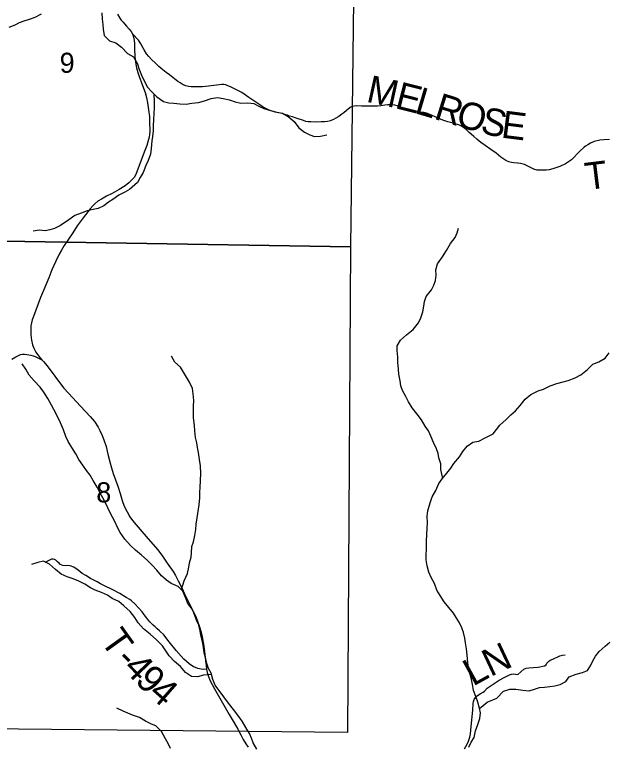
# Model space of a CAD drawing. Extents: x 0 to 34, y 0 to 22.
# Drawn here: x 25.315 to 26.547, y 15.526 to 17.051 of the extents above; entities that cross this region are included whole.
import ezdxf

# ---------------------------------------------------------------- set-up
doc = ezdxf.new("R2010")
doc.units = 0
for name, color, linetype in [('GM_X_Corporation', 7, 'Continuous'), ('GM_X_County_Road', 7, 'Continuous'), ('GM_X_Minor_River', 7, 'Continuous'), ('GM_X_Section_Text', 7, 'Continuous'), ('GM_X_Township_Road', 7, 'Continuous'), ('GM_X_Township_Road_Text', 7, 'Continuous')]:
    doc.layers.add(name, color=color, linetype=linetype)

msp = doc.modelspace()

# ---------------------------------------------------------------- linework, layer by layer
at = {"layer": 'GM_X_Corporation'}
for points in [[(26.0272, 17.5944), (26.0142, 16.5672), (24.9957, 16.5834), (25.0136, 17.617)], [(24.9957, 16.5834), (26.0142, 16.5672), (26.0085, 15.5549), (24.9795, 15.5656)]]:
    msp.add_lwpolyline(points, close=True, dxfattribs=at)
at = {"layer": 'GM_X_County_Road'}
for points in [[(25.5294, 17.0518), (25.5339, 17.0436), (25.537, 17.0394), (25.5399, 17.0357), (25.548, 17.0269), (25.5535, 17.0203), (25.5574, 17.0153), (25.5605, 17.0104), (25.5627, 17.0038), (25.5638, 16.9976), (25.5643, 16.9901), (25.5646, 16.9792), (25.5651, 16.9637), (25.5664, 16.9519), (25.5685, 16.9395), (25.5713, 16.9299), (25.574, 16.9219), (25.5763, 16.9159), (25.5787, 16.9103), (25.5834, 16.8976), (25.5865, 16.8881), (25.5893, 16.8777), (25.5916, 16.8666), (25.5937, 16.852), (25.5956, 16.8385), (25.5961, 16.8281), (25.5962, 16.8075), (25.5957, 16.8009), (25.5948, 16.7955), (25.5925, 16.7856), (25.59, 16.7779), (25.5846, 16.7638), (25.5697, 16.7231), (25.5667, 16.7164), (25.5636, 16.7116), (25.5584, 16.7057), (25.5527, 16.7005), (25.5448, 16.6943), (25.5323, 16.6862), (25.5179, 16.678), (25.5065, 16.6722), (25.4957, 16.6665), (25.4883, 16.6621), (25.482, 16.6566), (25.478, 16.6524), (25.4722, 16.6458), (25.4576, 16.6271), (25.445, 16.6103), (25.436, 16.5963), (25.4183, 16.5694), (25.4121, 16.5598), (25.4077, 16.5519), (25.4003, 16.5367), (25.3925, 16.5188), (25.3861, 16.5025), (25.3747, 16.4761), (25.3688, 16.4612), (25.3538, 16.4214), (25.3516, 16.4151), (25.35, 16.4088), (25.3489, 16.4021), (25.3484, 16.3938), (25.3483, 16.3836), (25.3498, 16.3722), (25.3519, 16.3628), (25.3548, 16.3559), (25.3589, 16.3476), (25.3647, 16.3395), (25.3712, 16.3316)], [(25.3712, 16.3316), (25.3753, 16.327), (25.3819, 16.3197), (25.3891, 16.3109), (25.4084, 16.2843), (25.4174, 16.2726), (25.427, 16.2621), (25.4519, 16.2351), (25.4724, 16.2137), (25.4813, 16.2031), (25.4887, 16.1913), (25.4922, 16.1843), (25.4974, 16.1739), (25.5009, 16.165), (25.5055, 16.1508), (25.5092, 16.135), (25.5129, 16.1188), (25.5166, 16.1061), (25.5203, 16.0948), (25.53, 16.0685), (25.5345, 16.0527), (25.5385, 16.0382), (25.5429, 16.0268), (25.5489, 16.0149), (25.5551, 16.0044), (25.5606, 15.9967), (25.5798, 15.9738), (25.598, 15.9529), (25.6132, 15.9356), (25.6228, 15.9225), (25.6329, 15.908), (25.645, 15.8903), (25.6498, 15.8822), (25.6557, 15.8711), (25.6638, 15.855), (25.6686, 15.8436), (25.6875, 15.8065), (25.6932, 15.7944), (25.696, 15.7871), (25.7002, 15.7748), (25.7033, 15.7641), (25.7056, 15.7545), (25.7089, 15.7347), (25.7113, 15.7178), (25.7125, 15.7053), (25.7134, 15.6989), (25.7138, 15.6948), (25.7147, 15.6871), (25.7162, 15.6799), (25.7181, 15.6735), (25.7217, 15.6642), (25.7262, 15.655), (25.7314, 15.6457), (25.7368, 15.6359), (25.7534, 15.6072), (25.7618, 15.5924), (25.772, 15.5754), (25.78, 15.5616), (25.7859, 15.5504), (25.7911, 15.5402), (25.7962, 15.5317), (25.801, 15.5244)]]:
    msp.add_lwpolyline(points, dxfattribs=at)
at = {"layer": 'GM_X_Minor_River'}
for points in [[(25.3703, 17.0513), (25.3567, 17.0449), (25.3453, 17.0406), (25.3339, 17.0368), (25.3245, 17.0334), (25.315, 17.0288), (25.3025, 17.0238)], [(25.4967, 17.0544), (25.4975, 17.0411), (25.4983, 17.0301), (25.499, 17.0206), (25.5014, 17.0074), (25.5124, 16.9964), (25.5253, 16.9919), (25.5375, 16.9828), (25.5496, 16.9695), (25.5625, 16.9628), (25.5709, 16.9484), (25.5732, 16.9381), (25.5793, 16.9245), (25.5847, 16.9127), (25.5915, 16.8998), (25.6003, 16.89), (25.6109, 16.8794), (25.6246, 16.8696), (25.636, 16.867), (25.6462, 16.8662), (25.6591, 16.8648), (25.6724, 16.8644), (25.6842, 16.866), (25.6975, 16.8679), (25.7104, 16.8714), (25.724, 16.8756), (25.7373, 16.8779), (25.7494, 16.876), (25.7623, 16.8734), (25.7741, 16.8693), (25.7863, 16.8663), (25.8003, 16.8671), (25.8132, 16.8656), (25.8238, 16.86), (25.8341, 16.8551), (25.8478, 16.8509), (25.861, 16.8476), (25.8728, 16.8453), (25.8846, 16.8385), (25.8968, 16.8279), (25.907, 16.8151), (25.9188, 16.806), (25.9295, 16.8003), (25.9397, 16.7966), (25.9518, 16.7977), (25.9655, 16.8001)], [(25.6046, 16.8856), (25.6056, 16.8695), (25.6057, 16.8562), (25.6049, 16.8437), (25.6042, 16.8331), (25.6035, 16.8183), (25.6031, 16.8088), (25.602, 16.797), (25.6009, 16.7875), (25.599, 16.7719), (25.5975, 16.7602), (25.593, 16.7469), (25.5881, 16.7362), (25.5824, 16.7218), (25.576, 16.7111), (25.5707, 16.7009), (25.5544, 16.6864), (25.5446, 16.6807), (25.5321, 16.6742), (25.5196, 16.6658), (25.5101, 16.6597), (25.5006, 16.6524), (25.4885, 16.6467), (25.4782, 16.6444), (25.4661, 16.6417), (25.4532, 16.6371), (25.4403, 16.6321), (25.4274, 16.6234), (25.4104, 16.6115), (25.3979, 16.6054), (25.388, 16.6024), (25.3782, 16.6004), (25.366, 16.6015), (25.3531, 16.5996)], [(26.2066, 16.0845), (26.203, 16.1031), (26.2026, 16.1149), (26.1988, 16.127), (26.1973, 16.1365), (26.1935, 16.146), (26.1874, 16.1589), (26.1817, 16.1722), (26.1767, 16.1832), (26.1702, 16.193), (26.1622, 16.2063), (26.1535, 16.2184), (26.1432, 16.2313), (26.1352, 16.2438), (26.1295, 16.2547), (26.123, 16.2673), (26.1196, 16.2771), (26.118, 16.2874), (26.1153, 16.3014), (26.1142, 16.312), (26.1134, 16.3264), (26.113, 16.3371), (26.1114, 16.3511), (26.1118, 16.3606), (26.1186, 16.3724), (26.1311, 16.3838), (26.1447, 16.3945), (26.1561, 16.4082), (26.161, 16.4188), (26.1651, 16.4317), (26.1674, 16.4431), (26.1689, 16.453), (26.1723, 16.4637), (26.1829, 16.4773), (26.1878, 16.4869), (26.1916, 16.4964), (26.1927, 16.5077), (26.1923, 16.5188), (26.1957, 16.5317), (26.2059, 16.5461), (26.2142, 16.5594), (26.2229, 16.5735), (26.2323, 16.5864), (26.2365, 16.5963), (26.2395, 16.6058)], [(26.3116, 16.1771), (26.3256, 16.1951), (26.3386, 16.2071), (26.3487, 16.2167), (26.3585, 16.2255), (26.3682, 16.2366), (26.3786, 16.2492), (26.3898, 16.2589), (26.4052, 16.2666), (26.4162, 16.2706), (26.4301, 16.2772), (26.4444, 16.2819), (26.4576, 16.2855), (26.4681, 16.2887), (26.4828, 16.2938), (26.4945, 16.3), (26.5083, 16.3112), (26.5195, 16.3223), (26.5319, 16.3274), (26.5451, 16.3347), (26.5533, 16.3458)], [(25.6621, 15.8531), (25.6682, 15.8707), (25.6749, 15.8866), (25.6776, 15.8992), (25.6791, 15.9087), (25.6825, 15.92), (25.6832, 15.9295), (25.6839, 15.9424), (25.6877, 15.9523), (25.69, 15.9652), (25.6922, 15.9778), (25.6933, 15.9888), (25.6948, 16.0025), (25.6993, 16.029), (25.7008, 16.0442), (25.7004, 16.0556), (25.7011, 16.0651), (25.7022, 16.0799), (25.7026, 16.0947), (25.7022, 16.1103), (25.7002, 16.1236), (25.6975, 16.1384), (25.6956, 16.1486), (25.6941, 16.1585), (25.6918, 16.1698), (25.6902, 16.1835), (25.6894, 16.1949), (25.6871, 16.2108), (25.6871, 16.2207), (25.6875, 16.2351), (25.6882, 16.2469), (25.687, 16.2609), (25.6855, 16.2719), (25.679, 16.2852), (25.6664, 16.306), (25.6603, 16.3163), (25.6486, 16.3268), (25.6413, 16.339)], [(25.4266, 16.161), (25.4212, 16.172), (25.4163, 16.1853), (25.4105, 16.2004), (25.4037, 16.2145), (25.3964, 16.2277), (25.3919, 16.2372), (25.3842, 16.2508), (25.3755, 16.2641), (25.3679, 16.2743), (25.3557, 16.2876), (25.3451, 16.2997), (25.3378, 16.3118), (25.3302, 16.3232)], [(26.2612, 15.5241), (26.2661, 15.5347), (26.2722, 15.5443), (26.2752, 15.5583), (26.2797, 15.5716), (26.2839, 15.5845), (26.285, 15.5959), (26.2831, 15.6054), (26.2796, 15.6179), (26.2754, 15.6297), (26.2705, 15.6422), (26.2685, 15.6551), (26.2655, 15.6687), (26.2632, 15.6782), (26.2605, 15.6877), (26.2586, 15.701), (26.2574, 15.7158), (26.2562, 15.7294), (26.2543, 15.742), (26.2528, 15.7514), (26.2501, 15.7632), (26.2467, 15.7734), (26.2417, 15.7837), (26.2348, 15.7943), (26.2291, 15.8037), (26.2196, 15.8151), (26.2093, 15.8272), (26.201, 15.8405), (26.1945, 15.8518), (26.1892, 15.8655), (26.1823, 15.878), (26.1777, 15.889), (26.1743, 15.9019), (26.172, 15.9144), (26.1723, 15.9243), (26.1731, 15.9372), (26.173, 15.9527), (26.1734, 15.9672), (26.1741, 15.9808), (26.1748, 15.9918), (26.1744, 16.0059), (26.1755, 16.0169), (26.1786, 16.0264), (26.1808, 16.0359), (26.1846, 16.0458), (26.1921, 16.0595), (26.1986, 16.0735), (26.2057, 16.0834), (26.2152, 16.0952), (26.2235, 16.1059), (26.23, 16.1154), (26.2413, 16.1295), (26.2485, 16.1405), (26.2576, 16.1519), (26.2693, 16.1599), (26.2815, 16.1622), (26.2947, 16.1691), (26.3116, 16.1771)], [(25.8192, 15.5204), (25.8116, 15.5333), (25.8085, 15.5432), (25.8039, 15.5526), (25.7963, 15.5655), (25.7887, 15.5788), (25.7796, 15.5913), (25.7704, 15.603), (25.7605, 15.6163), (25.7503, 15.6291), (25.7328, 15.6534), (25.7274, 15.6655), (25.724, 15.6788), (25.7186, 15.6882), (25.7152, 15.6985), (25.7121, 15.7114), (25.7095, 15.7212), (25.7083, 15.7326), (25.7064, 15.744), (25.7029, 15.7577), (25.701, 15.7671), (25.6983, 15.7785), (25.6938, 15.7888), (25.6903, 15.7986), (25.6854, 15.8111), (25.6758, 15.8236), (25.6705, 15.8361), (25.6655, 15.8498), (25.6557, 15.8592), (25.6412, 15.8656), (25.631, 15.8724), (25.6207, 15.8815), (25.6108, 15.8932), (25.6013, 15.9035), (25.5906, 15.9141), (25.5789, 15.9243), (25.5663, 15.9352), (25.5561, 15.9443), (25.5443, 15.9576), (25.5344, 15.972), (25.5294, 15.9818), (25.5241, 15.9932), (25.5187, 16.0034), (25.5126, 16.0155), (25.5054, 16.0307), (25.4985, 16.044), (25.4932, 16.0534), (25.4867, 16.0663), (25.4787, 16.08), (25.4723, 16.0909), (25.4646, 16.1012), (25.4566, 16.1122), (25.4487, 16.1239), (25.4426, 16.1353), (25.4342, 16.1485), (25.4266, 16.161)], [(25.7247, 15.676), (25.708, 15.6742), (25.6959, 15.6711), (25.6834, 15.6718), (25.6705, 15.6801), (25.6606, 15.6922), (25.6477, 15.7032), (25.637, 15.7149), (25.6301, 15.7252), (25.6225, 15.7354), (25.61, 15.7482), (25.5974, 15.7596), (25.583, 15.7709), (25.5723, 15.7838), (25.5651, 15.7948), (25.5552, 15.8073), (25.5423, 15.8186), (25.532, 15.8277), (25.5183, 15.8345), (25.5085, 15.8409), (25.4959, 15.847), (25.4826, 15.8515), (25.4728, 15.8567), (25.461, 15.8639), (25.4485, 15.8703), (25.4367, 15.8749), (25.4245, 15.8794), (25.412, 15.8846), (25.4002, 15.8945), (25.3877, 15.9054), (25.3747, 15.9119), (25.363, 15.9095), (25.3501, 15.9053)], [(26.3192, 15.6267), (26.3331, 15.6411), (26.3463, 15.645), (26.3588, 15.6456), (26.3732, 15.6435), (26.3865, 15.6417), (26.3978, 15.6453), (26.4083, 15.6484), (26.4185, 15.6497), (26.4295, 15.651), (26.44, 15.6523), (26.451, 15.6551), (26.4634, 15.6613), (26.4697, 15.6708), (26.4847, 15.6763), (26.4979, 15.6799), (26.5081, 15.6842), (26.5144, 15.6938), (26.5192, 15.704), (26.5248, 15.714), (26.5326, 15.7239), (26.5449, 15.7351), (26.5546, 15.7435)], [(26.2832, 15.6046), (26.2865, 15.6077), (26.2994, 15.6184), (26.3192, 15.6267)], [(25.6393, 15.5217), (25.6347, 15.5323), (25.629, 15.5418), (25.621, 15.557), (25.6092, 15.5687), (25.5997, 15.5725), (25.5876, 15.5785), (25.5751, 15.5864), (25.5606, 15.5913), (25.5507, 15.5951), (25.5409, 15.5996), (25.5276, 15.606)]]:
    msp.add_lwpolyline(points, dxfattribs=at)
at = {"layer": 'GM_X_Township_Road'}
for points in [[(26.0155, 16.8581), (26.0139, 16.8574), (26.0097, 16.854), (26.0063, 16.8507), (26.0009, 16.846), (25.9966, 16.843), (25.9904, 16.8385), (25.9841, 16.8347), (25.9794, 16.8321), (25.9758, 16.8305), (25.9728, 16.8295), (25.9668, 16.8281), (25.9601, 16.8276), (25.9533, 16.827), (25.9415, 16.8268), (25.9317, 16.827), (25.9262, 16.8274), (25.9212, 16.8282), (25.9165, 16.8298), (25.9013, 16.835), (25.8935, 16.8374), (25.8874, 16.8394), (25.883, 16.841), (25.8796, 16.8422), (25.8721, 16.8444), (25.8643, 16.8459), (25.8574, 16.8474), (25.8512, 16.8492), (25.8449, 16.8516), (25.8364, 16.856), (25.8307, 16.8595), (25.8253, 16.8628), (25.8192, 16.867), (25.8027, 16.8781), (25.7882, 16.8887), (25.7648, 16.9001), (25.7589, 16.9026), (25.7546, 16.9041), (25.7503, 16.9048), (25.7465, 16.9048), (25.7411, 16.9045), (25.7188, 16.9013), (25.7061, 16.9005), (25.6977, 16.9001), (25.689, 16.8999), (25.6824, 16.9003), (25.6767, 16.901), (25.6717, 16.9022), (25.6657, 16.9047), (25.6598, 16.9083), (25.6546, 16.9115), (25.6371, 16.9251), (25.6303, 16.9302), (25.6236, 16.9355), (25.6153, 16.9427), (25.6083, 16.9492), (25.6, 16.9572), (25.5943, 16.9633), (25.5896, 16.9693), (25.5846, 16.977), (25.5818, 16.9821), (25.5776, 16.9901), (25.5757, 16.9935), (25.5726, 16.9972), (25.5605, 17.0104)], [(26.5539, 16.7902), (26.542, 16.79), (26.5336, 16.7892), (26.5221, 16.7862), (26.5147, 16.7826), (26.5088, 16.7792), (26.5041, 16.7767), (26.5009, 16.7745), (26.492, 16.7664), (26.4749, 16.7483), (26.4626, 16.74), (26.4509, 16.7339), (26.4363, 16.7295), (26.4284, 16.7276), (26.4224, 16.7264), (26.4171, 16.7263), (26.4095, 16.7263), (26.4035, 16.7269), (26.3967, 16.7289), (26.3879, 16.7331), (26.3771, 16.7385), (26.3689, 16.7405), (26.3621, 16.7411), (26.3548, 16.7419), (26.3498, 16.7427), (26.344, 16.7442), (26.3383, 16.7469), (26.3278, 16.754), (26.3178, 16.7621), (26.3069, 16.7696), (26.2951, 16.7782), (26.2859, 16.7844), (26.2776, 16.7913), (26.2715, 16.7968), (26.2657, 16.8017), (26.2618, 16.8054), (26.2554, 16.8115), (26.248, 16.8168), (26.2445, 16.8189), (26.2413, 16.8203), (26.2283, 16.8242), (26.2175, 16.8272), (26.2071, 16.8306), (26.1909, 16.8374), (26.1783, 16.8435), (26.1725, 16.8455), (26.1675, 16.8466), (26.1587, 16.8476), (26.1492, 16.8478), (26.1452, 16.848), (26.141, 16.8486), (26.1372, 16.8498), (26.1321, 16.8517), (26.1185, 16.8579), (26.1115, 16.8607), (26.1065, 16.862), (26.1022, 16.8627), (26.0962, 16.8628), (26.0914, 16.8625), (26.0863, 16.862), (26.0779, 16.8609), (26.0708, 16.86), (26.0624, 16.8596), (26.054, 16.8596), (26.0474, 16.8597), (26.0376, 16.8602), (26.0263, 16.8603), (26.018, 16.859), (26.0155, 16.8581)], [(25.3088, 16.333), (25.317, 16.3374), (25.3232, 16.3406), (25.3271, 16.3423), (25.3315, 16.3432), (25.3353, 16.3433), (25.34, 16.3428), (25.3485, 16.3411), (25.3532, 16.3399), (25.3574, 16.3383), (25.3712, 16.3316)], [(25.7147, 15.6871), (25.7089, 15.6862), (25.7033, 15.6866), (25.6964, 15.6882), (25.6918, 15.6902), (25.6877, 15.6921), (25.6784, 15.6981), (25.6726, 15.7031), (25.6675, 15.7081), (25.6618, 15.7139), (25.651, 15.7259), (25.6366, 15.7438), (25.6253, 15.7587), (25.6168, 15.7671), (25.6112, 15.7718), (25.6075, 15.7748), (25.6032, 15.7787), (25.6007, 15.7813), (25.5967, 15.7857), (25.5898, 15.794), (25.5803, 15.8061), (25.5649, 15.8233), (25.5582, 15.8293), (25.5548, 15.8318), (25.5469, 15.8365), (25.5338, 15.8445), (25.5191, 15.8524), (25.5004, 15.8616), (25.4938, 15.8647), (25.4867, 15.8686), (25.4731, 15.8759), (25.4628, 15.8819), (25.4554, 15.8866), (25.4469, 15.8929), (25.4379, 15.8993), (25.4303, 15.9023), (25.4246, 15.9031), (25.4199, 15.9022), (25.4153, 15.9027), (25.4115, 15.904), (25.4093, 15.9058), (25.4073, 15.9078), (25.4044, 15.9107), (25.4005, 15.9137), (25.3979, 15.9151), (25.3952, 15.9158), (25.3919, 15.9159), (25.3888, 15.915), (25.3776, 15.9095)], [(26.2521, 15.5212), (26.2574, 15.5309), (26.2604, 15.537), (26.2619, 15.541), (26.263, 15.545), (26.2647, 15.5524), (26.2654, 15.5596), (26.2663, 15.5742), (26.2694, 15.6013), (26.2701, 15.6152), (26.2706, 15.6195), (26.2719, 15.6237), (26.2746, 15.628), (26.2769, 15.6306), (26.2844, 15.6353), (26.291, 15.6389), (26.2935, 15.6413), (26.2995, 15.6473), (26.3137, 15.6572), (26.3242, 15.6637), (26.3358, 15.6701), (26.3455, 15.6749), (26.3499, 15.6765), (26.3538, 15.6773), (26.3584, 15.6765), (26.363, 15.6761), (26.3756, 15.6871), (26.3807, 15.689), (26.3859, 15.6898), (26.4057, 15.6913), (26.4184, 15.6941), (26.4221, 15.6963), (26.4236, 15.6997), (26.4268, 15.7032), (26.4302, 15.7054), (26.4363, 15.7075), (26.4503, 15.7146), (26.456, 15.7164), (26.4614, 15.7167)]]:
    msp.add_lwpolyline(points, dxfattribs=at)

# ---------------------------------------------------------------- texts
at = {"layer": 'GM_X_Section_Text'}
for s, p in [('9', (25.4086, 16.9294)), ('8', (25.4849, 16.0344))]:
    msp.add_text(s, height=0.0419, rotation=0, dxfattribs=at).set_placement(p)
at = {"layer": 'GM_X_Township_Road_Text'}
for s, rotation, p in [('M', 347.6016, (26.0454, 16.8696)), ('E', 345.7361, (26.1051, 16.8564)), ('L', 343.4695, (26.1458, 16.8461)), ('R', 342.6944, (26.1863, 16.8341)), ('O', 343.2581, (26.2314, 16.82)), ('S', 346.7114, (26.2829, 16.8047)), ('E', 352.8017, (26.3267, 16.7947)), ('T', 7.0681, (26.5064, 16.685)), ('T', 305.6338, (25.492, 15.7458)), ('N', 25.1883, (26.3059, 15.6704)), ('-', 314.0172, (25.5226, 15.7043)), ('4', 313.6016, (25.5387, 15.6876)), ('L', 28.8157, (26.2695, 15.6504)), ('9', 314.6147, (25.5636, 15.6614)), ('4', 318.7621, (25.5915, 15.6334))]:
    msp.add_text(s, height=0.0568, rotation=rotation, dxfattribs=at).set_placement(p)

doc.saveas('drawing.dxf')
